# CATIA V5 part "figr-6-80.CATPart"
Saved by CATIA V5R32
Part number: Part1
Bounding box of the stored display mesh (mm): x -34 to 138.458, y -76 to 68, z 0 to 192.551
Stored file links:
  D:\PROJECTS\Project 2022\CATIA V5 6R 2022\Resources\Part Files\c06_catia_v5_6r2022_prt\figr-6-80.CATPart
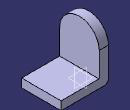
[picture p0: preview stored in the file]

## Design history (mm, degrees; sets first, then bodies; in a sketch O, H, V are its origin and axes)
Body1 (main body)
  Sketch1 on zx-plane, origin (0, 0, 0), H (-1, 0, 0), V (0, 0, 1)
    line L1 (-138.4578, 31.0171) -> (0, 31.0171)
    line L2 (0, 31.0171) -> (0, 0)
    line L3 (0, 0) -> (-138.4578, 0)
    line L4 (-138.4578, 0) -> (-138.4578, 31.0171)
    horizontal: L1 H, L3 H
    vertical: L2 V, L4 V
  Pad1: profile Sketch1, direction (0, 1, 0), length 68, opposite side length 76
  Sketch2 on face of Pad1 from Sketch1.L2, origin (0, 0, 0), H (0, -1, 0), V (0, 0, 1)
    point P1 (-68, 0)
    line L1 (-68, 0) -> (-68, 120.5512)
    arc A1 centre (4, 120.5512) radius 72 from (-68, 120.5512) to (76, 120.5512) cw
    line L2 (76, 120.5512) -> (76, 0)
    point P5 (76, 0)
    line L3 (76, 0) -> (-68, 0)
    reference projected line E1 (-68, 0) -> (-68, 31.0171) from edge [face of Pad1 from Sketch1.L2 | end face of Pad1]
    reference projected line E2 (76, 0) -> (76, 31.0171) from edge [start face of Pad1 | face of Pad1 from Sketch1.L2]
    reference projected line E3 (76, 0) -> (76, 31.0171) from edge [start face of Pad1 | face of Pad1 from Sketch1.L2]
    coincidence: P1 H, P5 H
    vertical: L1 V
    tangency: A1 L1, L2 A1, L1 E1, L2 E3
    horizontal: L3 H
    parallelism: L2 E2
  Pad2: profile Sketch2, direction (-1, 0, 0), length 34
  Shell1: ExtOffset 0, Face (end face of Pad2; face of Pad2), IntOffset 5
  Fillet1: radius 15, on edge [face of Pad2 | end face of Pad2] (x2)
